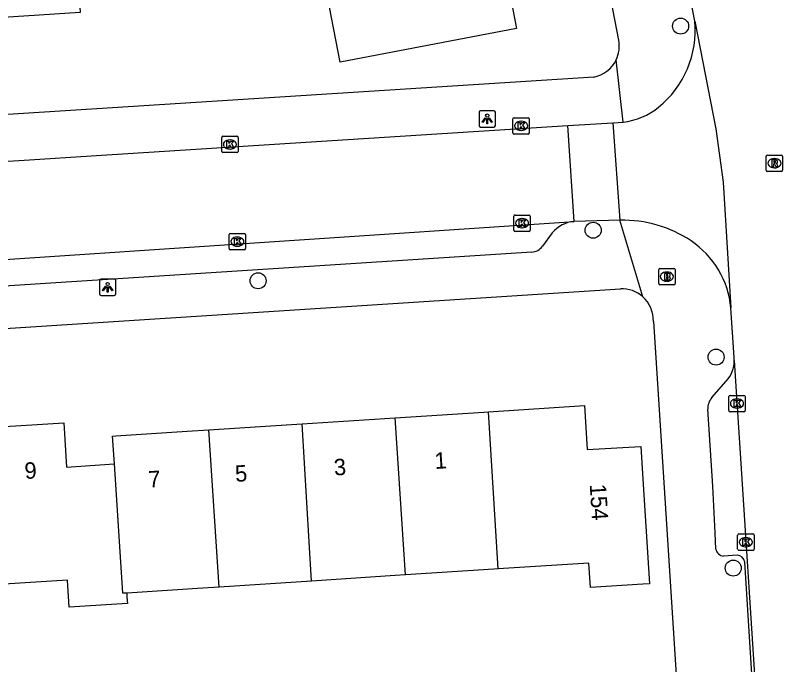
# Model space of a CAD drawing. Extents: x 159628 to 160723, y 388176 to 389416.
# Drawn here: x 160461.73 to 160508.53, y 388467.32 to 388506.93 of the extents above; entities that cross this region are included whole.
import ezdxf

# ---------------------------------------------------------------- set-up
doc = ezdxf.new("R2010")
doc.units = 0
for name, color, linetype in [('IMGEO_Boom', 7, 'Continuous'), ('IMGEO_Brandkraan', 7, 'Continuous'), ('IMGEO_Kolk', 7, 'Continuous'), ('IMGEO_Lichtpunt', 7, 'Continuous'), ('IMGEO_Pand', 7, 'Continuous'), ('IMGEO_Pand_nummerreeks', 7, 'Continuous'), ('IMGEO_Rijbaan_lokaal_gesloten', 7, 'Continuous'), ('IMGEO_Rijbaan_lokaal_open', 7, 'Continuous'), ('IMGEO_Rioolput', 7, 'Continuous'), ('IMGEO_Voetpad_open', 7, 'Continuous')]:
    doc.layers.add(name, color=color, linetype=linetype)

msp = doc.modelspace()

# ---------------------------------------------------------------- linework, layer by layer
at = {"layer": 'IMGEO_Boom'}
for centre in [(160502.309, 388506.278), (160496.975, 388493.818), (160476.536, 388490.735), (160504.471, 388486.083), (160505.517, 388473.209)]:
    msp.add_circle(centre, 0.489, dxfattribs=at)
at = {"layer": 'IMGEO_Brandkraan'}
for p, q in [((160500.971, 388490.565), (160500.971, 388491.417)), ((160501.046, 388491.491), (160501.898, 388491.491)), ((160501.459, 388491.271), (160501.484, 388491.271)), ((160501.972, 388491.417), (160501.972, 388490.565)), ((160501.482, 388490.711), (160501.457, 388490.711)), ((160501.898, 388490.491), (160501.046, 388490.491))]:
    msp.add_line(p, q, dxfattribs=at)
for points in [[(160500.971, 388490.565), (160500.971, 388491.417)], [(160501.046, 388491.491), (160501.898, 388491.491)], [(160501.319, 388491.191), (160501.319, 388490.791), (160501.532, 388490.791)], [(160501.55, 388491.191), (160501.319, 388491.191)], [(160501.498, 388491.11), (160501.444, 388491.11), (160501.444, 388491.034)], [(160501.972, 388491.417), (160501.972, 388490.565)], [(160501.444, 388491.034), (160501.497, 388491.034)], [(160501.506, 388490.958), (160501.444, 388490.958), (160501.444, 388490.877)], [(160501.444, 388490.877), (160501.506, 388490.877)], [(160501.898, 388490.491), (160501.046, 388490.491)]]:
    msp.add_lwpolyline(points, dxfattribs=at)
for centre, radius, start, end in [((160501.048, 388491.415), 0.0765, 91.552, 178.448), ((160501.048, 388491.415), 0.0765, 91.552, 178.448), ((160501.499, 388491.072), 0.0379, 267.8285, 90.9355), ((160501.554, 388491.046), 0.145, 59.4692, 91.5367), ((160501.579, 388491.093), 0.0922, 285.5137, 58.1501), ((160501.896, 388491.415), 0.0765, 1.552, 88.448), ((160501.896, 388491.415), 0.0765, 1.552, 88.448), ((160501.507, 388490.917), 0.0404, 269.8759, 90.5077), ((160501.538, 388491.042), 0.251, 268.6676, 293.5347), ((160501.584, 388490.901), 0.105, 301.3115, 78.989), ((160501.048, 388490.567), 0.0765, 181.552, 268.448), ((160501.048, 388490.567), 0.0765, 181.552, 268.448), ((160501.896, 388490.567), 0.0765, 271.552, 358.448), ((160501.896, 388490.567), 0.0765, 271.552, 358.448)]:
    msp.add_arc(centre, radius, start, end, dxfattribs=at)
for centre, major_axis, ratio, start_param, end_param in [((160501.458, 388490.991), (-0.387, 0.002), 0.722429, 4.712389, 7.853982), ((160501.483, 388490.991), (-0.39, 0.002), 0.717154, 1.570796, 4.712389)]:
    msp.add_ellipse(centre, major_axis=major_axis, ratio=ratio, start_param=start_param, end_param=end_param, dxfattribs=at)
at = {"layer": 'IMGEO_Kolk'}
for p, q in [((160492.079, 388499.761), (160492.079, 388500.613)), ((160492.154, 388500.687), (160493.006, 388500.687)), ((160492.567, 388500.467), (160492.592, 388500.467)), ((160493.08, 388500.613), (160493.08, 388499.761)), ((160474.39, 388499.555), (160475.242, 388499.555)), ((160493.006, 388499.687), (160492.154, 388499.687)), ((160492.59, 388499.907), (160492.565, 388499.907)), ((160474.315, 388498.629), (160474.315, 388499.481)), ((160474.803, 388499.335), (160474.828, 388499.335)), ((160475.316, 388499.481), (160475.316, 388498.629)), ((160474.826, 388498.775), (160474.801, 388498.775)), ((160475.242, 388498.555), (160474.39, 388498.555)), ((160492.137, 388493.824), (160492.137, 388494.676)), ((160492.212, 388494.75), (160493.064, 388494.75)), ((160492.625, 388494.53), (160492.65, 388494.53)), ((160493.138, 388494.676), (160493.138, 388493.824)), ((160492.648, 388493.97), (160492.623, 388493.97)), ((160474.773, 388492.699), (160474.773, 388493.551)), ((160474.848, 388493.625), (160475.7, 388493.625)), ((160475.774, 388493.551), (160475.774, 388492.699)), ((160493.064, 388493.75), (160492.212, 388493.75)), ((160475.261, 388493.405), (160475.286, 388493.405)), ((160475.7, 388492.625), (160474.848, 388492.625)), ((160475.284, 388492.845), (160475.259, 388492.845)), ((160505.246, 388482.82), (160505.246, 388483.672)), ((160505.321, 388483.746), (160506.173, 388483.746)), ((160506.247, 388483.672), (160506.247, 388482.82)), ((160505.734, 388483.526), (160505.759, 388483.526)), ((160506.173, 388482.746), (160505.321, 388482.746)), ((160505.757, 388482.966), (160505.732, 388482.966)), ((160505.788, 388474.364), (160505.788, 388475.216)), ((160505.863, 388475.29), (160506.715, 388475.29)), ((160506.789, 388475.216), (160506.789, 388474.364)), ((160506.276, 388475.07), (160506.301, 388475.07)), ((160506.715, 388474.29), (160505.863, 388474.29)), ((160506.299, 388474.51), (160506.274, 388474.51))]:
    msp.add_line(p, q, dxfattribs=at)
for points in [[(160492.079, 388499.761), (160492.079, 388500.613)], [(160492.154, 388500.687), (160493.006, 388500.687)], [(160493.08, 388500.613), (160493.08, 388499.761)], [(160492.4, 388500.387), (160492.523, 388500.387), (160492.523, 388500.236), (160492.653, 388500.387), (160492.817, 388500.387), (160492.671, 388500.236), (160492.824, 388499.987), (160492.672, 388499.987), (160492.587, 388500.151), (160492.523, 388500.084), (160492.523, 388499.987), (160492.4, 388499.987), (160492.4, 388500.387)], [(160474.39, 388499.555), (160475.242, 388499.555)], [(160493.006, 388499.687), (160492.154, 388499.687)], [(160474.315, 388498.629), (160474.315, 388499.481)], [(160474.636, 388499.255), (160474.759, 388499.255), (160474.759, 388499.104), (160474.889, 388499.255), (160475.053, 388499.255), (160474.907, 388499.104), (160475.06, 388498.855), (160474.908, 388498.855), (160474.823, 388499.019), (160474.759, 388498.952), (160474.759, 388498.855), (160474.636, 388498.855), (160474.636, 388499.255)], [(160475.316, 388499.481), (160475.316, 388498.629)], [(160475.242, 388498.555), (160474.39, 388498.555)], [(160492.137, 388493.824), (160492.137, 388494.676)], [(160492.212, 388494.75), (160493.064, 388494.75)], [(160492.458, 388494.45), (160492.581, 388494.45), (160492.581, 388494.299), (160492.711, 388494.45), (160492.875, 388494.45), (160492.729, 388494.299), (160492.882, 388494.05), (160492.73, 388494.05), (160492.645, 388494.214), (160492.581, 388494.147), (160492.581, 388494.05), (160492.458, 388494.05), (160492.458, 388494.45)], [(160493.138, 388494.676), (160493.138, 388493.824)], [(160474.773, 388492.699), (160474.773, 388493.551)], [(160474.848, 388493.625), (160475.7, 388493.625)], [(160475.774, 388493.551), (160475.774, 388492.699)], [(160493.064, 388493.75), (160492.212, 388493.75)], [(160475.094, 388493.325), (160475.217, 388493.325), (160475.217, 388493.174), (160475.347, 388493.325), (160475.511, 388493.325), (160475.365, 388493.174), (160475.518, 388492.925), (160475.366, 388492.925), (160475.281, 388493.089), (160475.217, 388493.022), (160475.217, 388492.925), (160475.094, 388492.925), (160475.094, 388493.325)], [(160475.7, 388492.625), (160474.848, 388492.625)], [(160505.246, 388482.82), (160505.246, 388483.672)], [(160505.321, 388483.746), (160506.173, 388483.746)], [(160506.247, 388483.672), (160506.247, 388482.82)], [(160505.567, 388483.446), (160505.69, 388483.446), (160505.69, 388483.295), (160505.82, 388483.446), (160505.984, 388483.446), (160505.838, 388483.295), (160505.991, 388483.046), (160505.839, 388483.046), (160505.754, 388483.21), (160505.69, 388483.143), (160505.69, 388483.046), (160505.567, 388483.046), (160505.567, 388483.446)], [(160506.173, 388482.746), (160505.321, 388482.746)], [(160505.788, 388474.364), (160505.788, 388475.216)], [(160505.863, 388475.29), (160506.715, 388475.29)], [(160506.789, 388475.216), (160506.789, 388474.364)], [(160506.109, 388474.99), (160506.232, 388474.99), (160506.232, 388474.839), (160506.362, 388474.99), (160506.526, 388474.99), (160506.38, 388474.839), (160506.533, 388474.59), (160506.381, 388474.59), (160506.296, 388474.754), (160506.232, 388474.687), (160506.232, 388474.59), (160506.109, 388474.59), (160506.109, 388474.99)], [(160506.715, 388474.29), (160505.863, 388474.29)]]:
    msp.add_lwpolyline(points, dxfattribs=at)
for centre, start, end in [((160492.156, 388500.611), 91.552, 178.448), ((160492.156, 388500.611), 91.552, 178.448), ((160493.004, 388500.611), 1.552, 88.448), ((160493.004, 388500.611), 1.552, 88.448), ((160474.392, 388499.479), 91.552, 178.448), ((160474.392, 388499.479), 91.552, 178.448), ((160475.24, 388499.479), 1.552, 88.448), ((160475.24, 388499.479), 1.552, 88.448), ((160492.156, 388499.763), 181.552, 268.448), ((160492.156, 388499.763), 181.552, 268.448), ((160493.004, 388499.763), 271.552, 358.448), ((160493.004, 388499.763), 271.552, 358.448), ((160474.392, 388498.631), 181.552, 268.448), ((160474.392, 388498.631), 181.552, 268.448), ((160475.24, 388498.631), 271.552, 358.448), ((160475.24, 388498.631), 271.552, 358.448), ((160492.214, 388494.674), 91.552, 178.448), ((160492.214, 388494.674), 91.552, 178.448), ((160493.062, 388494.674), 1.552, 88.448), ((160493.062, 388494.674), 1.552, 88.448), ((160474.85, 388493.549), 91.552, 178.448), ((160474.85, 388493.549), 91.552, 178.448), ((160475.698, 388493.549), 1.552, 88.448), ((160475.698, 388493.549), 1.552, 88.448), ((160492.214, 388493.826), 181.552, 268.448), ((160492.214, 388493.826), 181.552, 268.448), ((160493.062, 388493.826), 271.552, 358.448), ((160493.062, 388493.826), 271.552, 358.448), ((160474.85, 388492.701), 181.552, 268.448), ((160474.85, 388492.701), 181.552, 268.448), ((160475.698, 388492.701), 271.552, 358.448), ((160475.698, 388492.701), 271.552, 358.448), ((160505.323, 388483.67), 91.552, 178.448), ((160505.323, 388483.67), 91.552, 178.448), ((160506.171, 388483.67), 1.552, 88.448), ((160506.171, 388483.67), 1.552, 88.448), ((160505.323, 388482.822), 181.552, 268.448), ((160505.323, 388482.822), 181.552, 268.448), ((160506.171, 388482.822), 271.552, 358.448), ((160506.171, 388482.822), 271.552, 358.448), ((160505.865, 388475.214), 91.552, 178.448), ((160505.865, 388475.214), 91.552, 178.448), ((160506.713, 388475.214), 1.552, 88.448), ((160506.713, 388475.214), 1.552, 88.448), ((160505.865, 388474.366), 181.552, 268.448), ((160505.865, 388474.366), 181.552, 268.448), ((160506.713, 388474.366), 271.552, 358.448), ((160506.713, 388474.366), 271.552, 358.448)]:
    msp.add_arc(centre, 0.0765, start, end, dxfattribs=at)
for centre, major_axis, ratio, start_param, end_param in [((160492.566, 388500.187), (-0.387, 0.002), 0.722429, 4.712389, 7.853982), ((160492.591, 388500.187), (-0.39, 0.002), 0.717154, 1.570796, 4.712389), ((160474.802, 388499.055), (-0.387, 0.002), 0.722429, 4.712389, 7.853982), ((160474.827, 388499.055), (-0.39, 0.002), 0.717154, 1.570796, 4.712389), ((160492.624, 388494.25), (-0.387, 0.002), 0.722429, 4.712389, 7.853982), ((160492.649, 388494.25), (-0.39, 0.002), 0.717154, 1.570796, 4.712389), ((160475.26, 388493.125), (-0.387, 0.002), 0.722429, 4.712389, 7.853982), ((160475.285, 388493.125), (-0.39, 0.002), 0.717154, 1.570796, 4.712389), ((160505.733, 388483.246), (-0.387, 0.002), 0.722429, 4.712389, 7.853982), ((160505.758, 388483.246), (-0.39, 0.002), 0.717154, 1.570796, 4.712389), ((160506.275, 388474.79), (-0.387, 0.002), 0.722429, 4.712389, 7.853982), ((160506.3, 388474.79), (-0.39, 0.002), 0.717154, 1.570796, 4.712389)]:
    msp.add_ellipse(centre, major_axis=major_axis, ratio=ratio, start_param=start_param, end_param=end_param, dxfattribs=at)
at = {"layer": 'IMGEO_Lichtpunt'}
for p, q in [((160490.012, 388501.017), (160490.012, 388500.21)), ((160490.012, 388501.017), (160490.012, 388500.21)), ((160490.914, 388501.112), (160490.106, 388501.112)), ((160490.914, 388501.112), (160490.106, 388501.112)), ((160491.008, 388500.21), (160491.008, 388501.017)), ((160491.008, 388500.21), (160491.008, 388501.017)), ((160490.106, 388500.116), (160490.914, 388500.116)), ((160490.106, 388500.116), (160490.914, 388500.116)), ((160466.859, 388490.744), (160466.859, 388489.937)), ((160466.859, 388490.744), (160466.859, 388489.937)), ((160467.761, 388490.839), (160466.953, 388490.839)), ((160467.761, 388490.839), (160466.953, 388490.839)), ((160467.855, 388489.937), (160467.855, 388490.744)), ((160467.855, 388489.937), (160467.855, 388490.744)), ((160466.953, 388489.843), (160467.761, 388489.843)), ((160466.953, 388489.843), (160467.761, 388489.843))]:
    msp.add_line(p, q, dxfattribs=at)
for points in [[(160490.386, 388500.681), (160490.425, 388500.653), (160490.237, 388500.391), (160490.199, 388500.418), (160490.386, 388500.681)], [(160490.488, 388500.633), (160490.535, 388500.633), (160490.535, 388500.311), (160490.488, 388500.311), (160490.488, 388500.633)], [(160490.598, 388500.653), (160490.636, 388500.68), (160490.823, 388500.418), (160490.784, 388500.39), (160490.598, 388500.653)], [(160467.233, 388490.408), (160467.272, 388490.38), (160467.084, 388490.118), (160467.046, 388490.145), (160467.233, 388490.408)], [(160467.335, 388490.36), (160467.382, 388490.36), (160467.382, 388490.038), (160467.335, 388490.038), (160467.335, 388490.36)], [(160467.445, 388490.38), (160467.483, 388490.407), (160467.67, 388490.145), (160467.631, 388490.117), (160467.445, 388490.38)]]:
    msp.add_lwpolyline(points, dxfattribs=at)
for centre in [(160490.511, 388500.815), (160467.358, 388490.542)]:
    msp.add_circle(centre, 0.0994, dxfattribs=at)
for centre, start, end in [((160490.106, 388501.017), 90, 180), ((160490.106, 388501.017), 90, 180), ((160490.914, 388501.017), 0, 90), ((160490.914, 388501.017), 0, 90), ((160490.106, 388500.21), 180, 270), ((160490.106, 388500.21), 180, 270), ((160490.914, 388500.21), 270, 0), ((160490.914, 388500.21), 270, 360), ((160466.953, 388490.744), 90, 180), ((160466.953, 388490.744), 90, 180), ((160467.761, 388490.744), 0, 90), ((160467.761, 388490.744), 0, 90), ((160466.953, 388489.937), 180, 270), ((160466.953, 388489.937), 180, 270), ((160467.761, 388489.937), 270, 0), ((160467.761, 388489.937), 270, 360)]:
    msp.add_arc(centre, 0.0946, start, end, dxfattribs=at)
at = {"layer": 'IMGEO_Pand'}
for points in [[(160493.361, 388515.617), (160493.85, 388513.074), (160493.428, 388512.994), (160494.046, 388509.763), (160491.679, 388509.311), (160492.289, 388506.12), (160481.543, 388504.067), (160480.753, 388508.177), (160483.299, 388509.633), (160482.555, 388513.508)], [(160452.717, 388514.549), (160458.604, 388514.917), (160458.68, 388513.705), (160465.248, 388514.117), (160465.375, 388512.09), (160465.688, 388507.099), (160459.091, 388506.686), (160459.235, 388504.249), (160455.986, 388504.061), (160456.01, 388503.605), (160453.385, 388503.447)], [(160484.906, 388482.381), (160490.296, 388482.731), (160490.591, 388482.75)], [(160490.591, 388482.75), (160496.455, 388483.13), (160496.616, 388480.441), (160499.873, 388480.636), (160500, 388478.637), (160500.406, 388472.245), (160500, 388472.22), (160496.814, 388472.017), (160496.719, 388473.514), (160491.181, 388473.155)], [(160491.181, 388473.155), (160490.591, 388482.75)], [(160479.23, 388482.013), (160484.267, 388482.34), (160484.906, 388482.381)], [(160485.519, 388472.788), (160484.906, 388482.381)], [(160458.802, 388481.699), (160460.086, 388481.782), (160464.679, 388482.078), (160464.851, 388479.37), (160466.29, 388479.468), (160467.77, 388479.569)], [(160473.535, 388481.644), (160478.238, 388481.949), (160479.23, 388482.013)], [(160479.794, 388472.417), (160479.23, 388482.013)], [(160467.77, 388479.569), (160467.661, 388481.263), (160467.851, 388481.275), (160472.209, 388481.558), (160473.535, 388481.644)], [(160474.157, 388472.051), (160473.535, 388481.644)], [(160468.522, 388471.686), (160468.407, 388471.678), (160468.28, 388471.67), (160467.77, 388479.569)], [(160491.181, 388473.155), (160490.917, 388473.138), (160485.519, 388472.788)], [(160468.522, 388471.686), (160468.538, 388471.431), (160468.562, 388471.056), (160465.015, 388470.827), (160464.909, 388472.473), (160460.706, 388472.202), (160459.367, 388472.116)], [(160479.794, 388472.417), (160478.86, 388472.356), (160474.157, 388472.051)], [(160485.519, 388472.788), (160484.888, 388472.747), (160479.794, 388472.417)], [(160474.157, 388472.051), (160472.831, 388471.965), (160468.853, 388471.707), (160468.522, 388471.686)]]:
    msp.add_lwpolyline(points, dxfattribs=at)
at = {"layer": 'IMGEO_Rijbaan_lokaal_gesloten'}
for points in [[(160503.185, 388506.569), (160502.955, 388507.741)], [(160503.185, 388506.569), (160504.456, 388500), (160504.895, 388496.745), (160505.375, 388489.092)], [(160505.579, 388485.867), (160505.566, 388486.065), (160505.375, 388489.092)], [(160505.579, 388485.867), (160507.212, 388460.409)]]:
    msp.add_lwpolyline(points, dxfattribs=at)
at = {"layer": 'IMGEO_Rijbaan_lokaal_open'}
for points in [[(160440.598, 388496.733), (160441.111, 388496.765), (160444.94, 388497.008), (160462.595, 388498.126), (160466.352, 388498.364), (160495.436, 388500.206)], [(160495.436, 388500.206), (160498.181, 388500.38)], [(160495.812, 388494.356), (160495.436, 388500.206)], [(160498.181, 388500.38), (160498.8, 388500.421)], [(160498.181, 388500.38), (160498.61, 388494.425)], [(160498.61, 388494.425), (160495.812, 388494.356)], [(160440.965, 388490.684), (160495.812, 388494.356)]]:
    msp.add_lwpolyline(points, dxfattribs=at)
for centre, radius, start, end in [((160497.077, 388506.058), 6.13, 309.4085, 4.7807), ((160498.326, 388504.62), 4.226, 276.4404, 308.6942), ((160498.83, 388487.077), 7.352, 55.9937, 91.7176), ((160499.843, 388488.557), 5.558, 5.5216, 56.108)]:
    msp.add_arc(centre, radius, start, end, dxfattribs=at)
at = {"layer": 'IMGEO_Rioolput'}
for p, q in [((160507.531, 388497.482), (160507.531, 388498.334)), ((160507.606, 388498.408), (160508.458, 388498.408)), ((160508.019, 388498.188), (160508.044, 388498.188)), ((160508.532, 388498.334), (160508.532, 388497.482)), ((160508.458, 388497.408), (160507.606, 388497.408)), ((160508.042, 388497.628), (160508.017, 388497.628))]:
    msp.add_line(p, q, dxfattribs=at)
for points in [[(160507.531, 388497.482), (160507.531, 388498.334)], [(160507.606, 388498.408), (160508.458, 388498.408)], [(160508.532, 388498.334), (160508.532, 388497.482)], [(160508.12, 388498.106), (160507.868, 388498.108), (160507.868, 388497.708)], [(160507.868, 388497.708), (160507.992, 388497.708), (160507.992, 388497.87), (160508.003, 388497.87)], [(160508.046, 388498.027), (160507.992, 388498.027), (160507.992, 388497.946)], [(160507.992, 388497.946), (160508.044, 388497.946)], [(160508.05, 388497.841), (160508.121, 388497.708), (160508.261, 388497.708), (160508.196, 388497.834)], [(160508.458, 388497.408), (160507.606, 388497.408)]]:
    msp.add_lwpolyline(points, dxfattribs=at)
for centre, radius, start, end in [((160507.608, 388498.332), 0.0765, 91.552, 178.448), ((160507.608, 388498.332), 0.0765, 91.552, 178.448), ((160508.456, 388498.332), 0.0765, 1.552, 88.448), ((160508.456, 388498.332), 0.0765, 1.552, 88.448), ((160508.002, 388497.817), 0.0533, 26.0293, 88.6989), ((160508.028, 388498.135), 0.19, 274.7715, 282.9687), ((160508.052, 388497.931), 0.0964, 77.0061, 93.1865), ((160508.066, 388497.988), 0.0378, 276.6634, 79.6772), ((160508.119, 388497.996), 0.109, 350.3612, 89.416), ((160508.117, 388497.996), 0.112, 277.5842, 350.9817), ((160508.101, 388497.781), 0.108, 29.5134, 73.7905), ((160507.608, 388497.484), 0.0765, 181.552, 268.448), ((160507.608, 388497.484), 0.0765, 181.552, 268.448), ((160508.456, 388497.484), 0.0765, 271.552, 358.448), ((160508.456, 388497.484), 0.0765, 271.552, 358.448)]:
    msp.add_arc(centre, radius, start, end, dxfattribs=at)
for centre, major_axis, ratio, start_param, end_param in [((160508.018, 388497.908), (-0.387, 0.002), 0.722429, 4.712389, 7.853982), ((160508.043, 388497.908), (-0.39, 0.002), 0.717154, 1.570796, 4.712389)]:
    msp.add_ellipse(centre, major_axis=major_axis, ratio=ratio, start_param=start_param, end_param=end_param, dxfattribs=at)
at = {"layer": 'IMGEO_Voetpad_open'}
for points in [[(160498.535, 388505.413), (160484.44, 388578.192), (160478.871, 388606.944)], [(160498.8, 388500.421), (160498.377, 388504.218)], [(160497.005, 388503.162), (160447.533, 388500), (160440.696, 388499.563)], [(160500, 388489.761), (160498.61, 388494.425)], [(160494.479, 388493.669), (160493.877, 388492.844)], [(160493.227, 388492.487), (160446.211, 388489.462), (160441.086, 388489.116)], [(160433.934, 388486.077), (160498.648, 388490.246)], [(160500.653, 388488.259), (160502.409, 388460.978)], [(160504.214, 388483.611), (160505.091, 388484.618)], [(160504.455, 388474.368), (160504.424, 388475.362), (160504.27, 388478.211), (160503.972, 388482.895)], [(160505.755, 388474.004), (160504.933, 388473.94)], [(160506.926, 388462.536), (160506.233, 388473.579)]]:
    msp.add_lwpolyline(points, dxfattribs=at)
for centre, radius, start, end in [((160496.644, 388505.055), 1.924, 334.2175, 10.7188), ((160496.644, 388505.05), 1.922, 280.8131, 334.3563), ((160495.998, 388492.359), 2.005, 95.3102, 139.221), ((160493.165, 388493.37), 0.885, 274.0004, 323.5535), ((160498.724, 388488.331), 1.917, 48.2585, 92.2729), ((160498.627, 388488.271), 2.026, 359.6573, 47.337), ((160503.768, 388485.855), 1.811, 316.9279, 0.3897), ((160504.96, 388482.96), 0.99, 138.8899, 183.7607), ((160504.99, 388474.485), 0.548, 192.334, 263.9837), ((160505.698, 388473.458), 0.549, 12.7007, 84.0174)]:
    msp.add_arc(centre, radius, start, end, dxfattribs=at)

# ---------------------------------------------------------------- texts
at = {"layer": 'IMGEO_Pand_nummerreeks'}
for s, rotation, p in [('3', 3.7094, (160481.19, 388478.853)), ('1', 3.7094, (160487.333, 388479.251)), ('9', 3.6898, (160462.319, 388478.64)), ('5', 3.7094, (160475.161, 388478.462)), ('7', 3.707, (160469.873, 388478.12)), ('154', 273.6346, (160496.763, 388478.317))]:
    msp.add_text(s, height=1, rotation=rotation, dxfattribs=at).set_placement(p)

doc.saveas('drawing.dxf')
